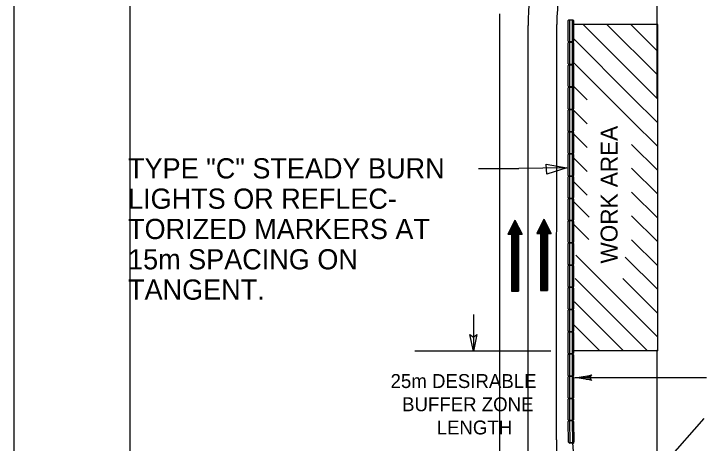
# Model space of a CAD drawing. Extents: x 2171 to 2395, y 134 to 413.
# Drawn here: x 2178.7 to 2238.8, y 319.6 to 356.6 of the extents above; entities that cross this region are included whole.
import ezdxf

# ---------------------------------------------------------------- set-up
doc = ezdxf.new("R2010")
doc.units = 0
for name, color, linetype in [('Level 10', 7, 'Continuous'), ('Level 12', 7, 'Continuous'), ('Level 2', 7, 'Continuous'), ('Level 20', 7, 'Continuous'), ('Level 4', 7, 'Continuous'), ('Level 5', 7, 'Continuous'), ('Level 60', 7, 'Continuous')]:
    doc.layers.add(name, color=color, linetype=linetype)

msp = doc.modelspace()

# ---------------------------------------------------------------- linework, layer by layer
at = {"layer": 'Level 10'}
for p, q in [((2220.618, 353.23), (2220.618, 356.607)), ((2234.222, 355.706), (2226.963, 355.706)), ((2226.963, 327.562), (2226.963, 355.706)), ((2234.222, 349.278), (2227.794, 355.706)), ((2234.222, 351.33), (2229.847, 355.706)), ((2234.222, 353.383), (2231.899, 355.706)), ((2234.222, 327.588), (2234.222, 355.706)), ((2223.061, 316.436), (2223.061, 355.61)), ((2232.007, 349.439), (2226.963, 354.483)), ((2220.618, 321.299), (2220.618, 353.23)), ((2232.086, 347.308), (2226.963, 352.431)), ((2228.139, 349.202), (2226.963, 350.378)), ((2234.222, 347.225), (2231.977, 349.47)), ((2228.139, 347.15), (2226.963, 348.326)), ((2234.222, 345.172), (2231.977, 347.417)), ((2228.139, 345.097), (2226.963, 346.273)), ((2234.222, 343.12), (2231.977, 345.365)), ((2228.139, 343.044), (2226.963, 344.22)), ((2218.779, 343.303), (2222.263, 343.303)), ((2226.386, 343.338), (2222.263, 343.303)), ((2234.222, 341.067), (2231.977, 343.312)), ((2228.139, 340.991), (2226.963, 342.168)), ((2234.222, 339.015), (2231.977, 341.259)), ((2228.324, 339.091), (2226.923, 340.491)), ((2221.917, 338.85), (2221.303, 337.622)), ((2221.917, 338.85), (2221.917, 332.714)), ((2221.917, 338.85), (2222.53, 337.622)), ((2224.422, 338.917), (2223.808, 337.69)), ((2224.422, 338.917), (2224.422, 332.781)), ((2224.422, 338.917), (2225.035, 337.69)), ((2234.222, 336.962), (2231.977, 339.206)), ((2221.611, 338.236), (2221.611, 332.714)), ((2221.687, 338.389), (2221.687, 332.714)), ((2221.762, 338.542), (2221.762, 332.714)), ((2221.841, 338.696), (2221.841, 332.714)), ((2221.993, 338.696), (2221.993, 332.714)), ((2222.07, 338.542), (2222.07, 332.714)), ((2222.147, 338.389), (2222.147, 332.714)), ((2222.224, 338.236), (2222.224, 332.714)), ((2224.116, 338.303), (2224.116, 332.781)), ((2224.192, 338.456), (2224.192, 332.781)), ((2224.268, 338.61), (2224.268, 332.781)), ((2224.346, 338.763), (2224.346, 332.781)), ((2224.498, 338.763), (2224.498, 332.781)), ((2224.575, 338.61), (2224.575, 332.781)), ((2224.652, 338.456), (2224.652, 332.781)), ((2224.729, 338.303), (2224.729, 332.781)), ((2228.276, 337.174), (2226.875, 338.575)), ((2221.303, 337.622), (2221.611, 337.622)), ((2221.38, 337.776), (2221.38, 337.622)), ((2221.456, 337.929), (2221.456, 337.622)), ((2221.533, 338.083), (2221.533, 337.622)), ((2221.611, 337.622), (2221.611, 332.714)), ((2222.224, 337.622), (2222.224, 332.714)), ((2222.224, 337.622), (2222.53, 337.622)), ((2222.3, 338.083), (2222.3, 337.622)), ((2222.377, 337.929), (2222.377, 337.622)), ((2222.454, 337.776), (2222.454, 337.622)), ((2223.808, 337.69), (2224.116, 337.69)), ((2223.885, 337.843), (2223.885, 337.69)), ((2223.961, 337.997), (2223.961, 337.69)), ((2224.038, 338.15), (2224.038, 337.69)), ((2224.116, 337.69), (2224.116, 332.781)), ((2224.729, 337.69), (2224.729, 332.781)), ((2224.729, 337.69), (2225.035, 337.69)), ((2224.806, 338.15), (2224.806, 337.69)), ((2224.882, 337.997), (2224.882, 337.69)), ((2224.959, 337.843), (2224.959, 337.69)), ((2234.222, 334.909), (2231.977, 337.154)), ((2234.222, 328.751), (2227.156, 335.817)), ((2234.222, 332.857), (2231.421, 335.658)), ((2233.324, 327.596), (2227.112, 333.809)), ((2234.222, 330.804), (2231.215, 333.811)), ((2221.611, 332.714), (2222.224, 332.714)), ((2224.116, 332.781), (2224.729, 332.781)), ((2231.253, 327.615), (2227.062, 331.807)), ((2229.181, 327.634), (2227.016, 329.798)), ((2234.222, 327.588), (2226.963, 327.588)), ((2234.222, 327.681), (2234.13, 327.589)), ((2220.618, 316.779), (2220.618, 321.81))]:
    msp.add_line(p, q, dxfattribs=at)
for points in [[(2224.62, 343.663), (2226.386, 343.338), (2224.675, 342.794)], [(2218.345, 327.544), (2218.043, 328.997), (2218.343, 328.757), (2218.643, 328.997)]]:
    msp.add_lwpolyline(points, close=True, dxfattribs=at)
at = {"layer": 'Level 12'}
for centre, radius, start, end in [((2245.532, 355.695), 20, 150.60658, 179.96375), ((2253.061, 355.61), 30, 161.99953, 180), ((2275.509, 319.886), 50, 179.96375, 194.28707)]:
    msp.add_arc(centre, radius, start, end, dxfattribs=at)
at = {"layer": 'Level 2'}
for p, q in [((2218.345, 330.718), (2218.345, 327.544)), ((2225.006, 327.544), (2213.297, 327.544))]:
    msp.add_line(p, q, dxfattribs=at)
at = {"layer": 'Level 20'}
for p, q in [((2234.164, 349.415), (2234.164, 399.312)), ((2234.164, 177.843), (2234.164, 327.612))]:
    msp.add_line(p, q, dxfattribs=at)
at = {"layer": 'Level 4'}
for p, q in [((2225.509, 319.917), (2225.532, 355.707)), ((2226.499, 354.26), (2226.5, 356.048)), ((2226.5, 356.048), (2226.566, 356.113)), ((2226.566, 356.113), (2226.897, 356.112)), ((2226.616, 356.113), (2226.613, 354.195)), ((2226.845, 356.114), (2226.843, 354.194)), ((2226.963, 356.048), (2226.897, 356.112)), ((2226.963, 356.048), (2226.961, 354.259)), ((2226.564, 354.195), (2226.499, 354.26)), ((2226.499, 352.321), (2226.5, 354.108)), ((2226.5, 354.108), (2226.566, 354.173)), ((2226.895, 354.195), (2226.564, 354.195)), ((2226.566, 354.173), (2226.897, 354.173)), ((2226.616, 354.173), (2226.613, 352.256)), ((2226.845, 354.174), (2226.843, 352.255)), ((2226.961, 354.259), (2226.895, 354.195)), ((2226.963, 354.109), (2226.897, 354.173)), ((2226.963, 354.109), (2226.961, 352.32)), ((2226.564, 352.255), (2226.499, 352.321)), ((2226.499, 350.382), (2226.5, 352.169)), ((2226.5, 352.169), (2226.566, 352.234)), ((2226.895, 352.256), (2226.564, 352.255)), ((2226.566, 352.234), (2226.897, 352.234)), ((2226.616, 352.234), (2226.613, 350.317)), ((2226.845, 352.235), (2226.843, 350.316)), ((2226.961, 352.32), (2226.895, 352.256)), ((2226.963, 352.169), (2226.897, 352.234)), ((2226.963, 352.169), (2226.961, 350.381)), ((2226.564, 350.316), (2226.499, 350.382)), ((2226.499, 348.441), (2226.5, 350.228)), ((2226.5, 350.228), (2226.566, 350.293)), ((2226.895, 350.317), (2226.564, 350.316)), ((2226.566, 350.293), (2226.897, 350.293)), ((2226.616, 350.293), (2226.613, 348.376)), ((2226.845, 350.294), (2226.843, 348.375)), ((2226.961, 350.381), (2226.895, 350.317)), ((2226.963, 350.229), (2226.897, 350.293)), ((2226.963, 350.229), (2226.961, 348.44)), ((2226.564, 348.376), (2226.499, 348.441)), ((2226.961, 348.44), (2226.895, 348.376)), ((2226.499, 346.524), (2226.5, 348.312)), ((2226.5, 348.312), (2226.566, 348.377)), ((2226.895, 348.376), (2226.564, 348.376)), ((2226.566, 348.377), (2226.897, 348.377)), ((2226.616, 348.377), (2226.613, 346.46)), ((2226.845, 348.378), (2226.843, 346.458)), ((2226.963, 348.312), (2226.897, 348.377)), ((2226.963, 348.312), (2226.961, 346.524)), ((2226.564, 346.459), (2226.499, 346.524)), ((2226.499, 344.609), (2226.5, 346.397)), ((2226.5, 346.397), (2226.566, 346.462)), ((2226.895, 346.46), (2226.564, 346.459)), ((2226.566, 346.462), (2226.897, 346.462)), ((2226.616, 346.462), (2226.613, 344.545)), ((2226.845, 346.463), (2226.843, 344.543)), ((2226.961, 346.524), (2226.895, 346.46)), ((2226.963, 346.397), (2226.897, 346.462)), ((2226.963, 346.397), (2226.961, 344.609)), ((2226.564, 344.544), (2226.499, 344.609)), ((2226.499, 342.694), (2226.5, 344.482)), ((2226.5, 344.482), (2226.566, 344.547)), ((2226.895, 344.544), (2226.564, 344.544)), ((2226.566, 344.547), (2226.897, 344.546)), ((2226.616, 344.547), (2226.613, 342.629)), ((2226.845, 344.548), (2226.843, 342.628)), ((2226.961, 344.609), (2226.895, 344.544)), ((2226.963, 344.482), (2226.897, 344.546)), ((2226.963, 344.482), (2226.961, 342.693)), ((2226.564, 342.629), (2226.499, 342.694)), ((2226.499, 340.779), (2226.5, 342.567)), ((2226.5, 342.567), (2226.566, 342.632)), ((2226.895, 342.629), (2226.564, 342.629)), ((2226.566, 342.632), (2226.897, 342.631)), ((2226.616, 342.632), (2226.613, 340.714)), ((2226.845, 342.632), (2226.843, 340.713)), ((2226.961, 342.693), (2226.895, 342.629)), ((2226.963, 342.567), (2226.897, 342.631)), ((2226.963, 342.567), (2226.961, 340.778)), ((2226.564, 340.714), (2226.499, 340.779)), ((2226.499, 338.864), (2226.5, 340.652)), ((2226.5, 340.652), (2226.566, 340.717)), ((2226.895, 340.714), (2226.564, 340.714)), ((2226.566, 340.717), (2226.897, 340.716)), ((2226.616, 340.717), (2226.613, 338.799)), ((2226.845, 340.717), (2226.843, 338.798)), ((2226.961, 340.778), (2226.895, 340.714)), ((2226.963, 340.652), (2226.897, 340.716)), ((2226.963, 340.652), (2226.961, 338.863)), ((2226.564, 338.799), (2226.499, 338.864)), ((2226.961, 338.863), (2226.895, 338.799)), ((2226.499, 336.949), (2226.5, 338.737)), ((2226.5, 338.737), (2226.566, 338.802)), ((2226.895, 338.799), (2226.564, 338.799)), ((2226.566, 338.802), (2226.897, 338.801)), ((2226.616, 338.802), (2226.613, 336.884)), ((2226.845, 338.802), (2226.843, 336.883)), ((2226.963, 338.737), (2226.897, 338.801)), ((2226.963, 338.737), (2226.961, 336.948)), ((2226.564, 336.884), (2226.499, 336.949)), ((2226.499, 335.034), (2226.5, 336.821)), ((2226.5, 336.821), (2226.566, 336.886)), ((2226.895, 336.884), (2226.564, 336.884)), ((2226.566, 336.886), (2226.897, 336.886)), ((2226.616, 336.886), (2226.613, 334.969)), ((2226.845, 336.887), (2226.843, 334.968)), ((2226.961, 336.948), (2226.895, 336.884)), ((2226.963, 336.822), (2226.897, 336.886)), ((2226.963, 336.822), (2226.961, 335.033)), ((2226.564, 334.968), (2226.499, 335.034)), ((2226.499, 333.119), (2226.5, 334.906)), ((2226.5, 334.906), (2226.566, 334.971)), ((2226.895, 334.969), (2226.564, 334.968)), ((2226.566, 334.971), (2226.897, 334.971)), ((2226.616, 334.971), (2226.613, 333.054)), ((2226.845, 334.972), (2226.843, 333.053)), ((2226.961, 335.033), (2226.895, 334.969)), ((2226.963, 334.906), (2226.897, 334.971)), ((2226.963, 334.906), (2226.961, 333.118)), ((2226.564, 333.053), (2226.499, 333.119)), ((2226.499, 331.204), (2226.5, 332.991)), ((2226.5, 332.991), (2226.566, 333.056)), ((2226.895, 333.054), (2226.564, 333.053)), ((2226.566, 333.056), (2226.897, 333.056)), ((2226.616, 333.056), (2226.613, 331.139)), ((2226.845, 333.057), (2226.843, 331.138)), ((2226.961, 333.118), (2226.895, 333.054)), ((2226.963, 332.991), (2226.897, 333.056)), ((2226.963, 332.991), (2226.961, 331.203)), ((2226.564, 331.138), (2226.499, 331.204)), ((2226.499, 329.289), (2226.5, 331.076)), ((2226.5, 331.076), (2226.566, 331.141)), ((2226.895, 331.139), (2226.564, 331.138)), ((2226.566, 331.141), (2226.897, 331.141)), ((2226.616, 331.141), (2226.613, 329.224)), ((2226.845, 331.142), (2226.843, 329.223)), ((2226.961, 331.203), (2226.895, 331.139)), ((2226.963, 331.076), (2226.897, 331.141)), ((2226.963, 331.076), (2226.961, 329.288)), ((2226.564, 329.223), (2226.499, 329.289)), ((2226.5, 329.161), (2226.566, 329.226)), ((2226.895, 329.224), (2226.564, 329.223)), ((2226.566, 329.226), (2226.897, 329.226)), ((2226.616, 329.226), (2226.613, 327.309)), ((2226.845, 329.227), (2226.843, 327.307)), ((2226.961, 329.288), (2226.895, 329.224)), ((2226.963, 329.161), (2226.897, 329.226)), ((2226.499, 327.373), (2226.5, 329.161)), ((2226.963, 329.161), (2226.961, 327.373)), ((2226.564, 327.308), (2226.499, 327.373)), ((2226.499, 325.458), (2226.5, 327.246)), ((2226.5, 327.246), (2226.566, 327.311)), ((2226.895, 327.309), (2226.564, 327.308)), ((2226.566, 327.311), (2226.897, 327.311)), ((2226.616, 327.311), (2226.613, 325.394)), ((2226.845, 327.312), (2226.843, 325.392)), ((2226.961, 327.373), (2226.895, 327.309)), ((2226.963, 327.246), (2226.897, 327.311)), ((2226.963, 327.246), (2226.961, 325.458)), ((2226.564, 325.393), (2226.499, 325.458)), ((2226.499, 323.543), (2226.5, 325.331)), ((2226.5, 325.331), (2226.566, 325.396)), ((2226.895, 325.393), (2226.564, 325.393)), ((2226.566, 325.396), (2226.897, 325.395)), ((2226.616, 325.396), (2226.613, 323.478)), ((2226.845, 325.397), (2226.843, 323.477)), ((2226.961, 325.458), (2226.895, 325.393)), ((2226.963, 325.331), (2226.897, 325.395)), ((2226.963, 325.331), (2226.961, 323.542)), ((2226.564, 323.478), (2226.499, 323.543)), ((2226.499, 321.628), (2226.5, 323.416)), ((2226.5, 323.416), (2226.566, 323.481)), ((2226.895, 323.478), (2226.564, 323.478)), ((2226.566, 323.481), (2226.897, 323.48)), ((2226.616, 323.481), (2226.613, 321.563)), ((2226.845, 323.482), (2226.843, 321.562)), ((2226.961, 323.542), (2226.895, 323.478)), ((2226.963, 323.416), (2226.897, 323.48)), ((2226.963, 323.416), (2226.961, 321.627)), ((2226.564, 321.563), (2226.499, 321.628)), ((2226.501, 321.492), (2226.566, 321.558)), ((2226.532, 319.705), (2226.501, 321.492)), ((2226.895, 321.563), (2226.564, 321.563)), ((2226.566, 321.558), (2226.897, 321.564)), ((2226.616, 321.559), (2226.648, 319.642)), ((2226.845, 321.564), (2226.878, 319.645)), ((2226.961, 321.627), (2226.895, 321.563)), ((2226.964, 321.5), (2226.897, 321.564)), ((2226.964, 321.5), (2226.994, 319.712)), ((2226.599, 319.64), (2226.532, 319.705)), ((2226.599, 319.622), (2226.929, 319.649)), ((2226.93, 319.647), (2226.599, 319.64)), ((2226.878, 319.645), (2227.034, 317.733)), ((2227, 319.59), (2226.929, 319.649)), ((2226.994, 319.712), (2226.93, 319.647))]:
    msp.add_line(p, q, dxfattribs=at)
at = {"layer": 'Level 5'}
for p, q in [((2238.436, 325.266), (2227.083, 325.266)), ((2228.056, 325.147), (2228.384, 325.148)), ((2228.074, 325.388), (2228.403, 325.39)), ((2238.207, 321.737), (2229.185, 311.591))]:
    msp.add_line(p, q, dxfattribs=at)
for centre, radius, start, end in [((2226.429, 333.535), 8.296, 274.51899, 284.68596), ((2226.392, 316.583), 8.709, 75.76919, 85.4469), ((2228.714, 325.267), 0.303, 126.74551, 233.23353)]:
    msp.add_arc(centre, radius, start, end, dxfattribs=at)
at = {"layer": 'Level 60'}
for points in [[(2394.748, 412.757), (2178.748, 412.757), (2178.748, 133.757), (2394.748, 133.757)], [(2375.622, 401.948), (2188.748, 401.948), (2188.748, 144.566), (2375.622, 144.566)]]:
    msp.add_lwpolyline(points, close=True, dxfattribs=at)

# ---------------------------------------------------------------- texts
at = {"layer": 'Level 10'}
msp.add_text('WORK AREA', height=1.4514, rotation=90, dxfattribs=at).set_placement((2230.759, 335.102))
for s, p in [('TYPE "C" STEADY BURN ', (2188.582, 342.432)), ('LIGHTS OR REFLEC-', (2188.582, 339.82)), ('TORIZED MARKERS AT ', (2188.582, 337.208)), ('15m SPACING ON ', (2188.582, 334.596)), ('TANGENT.', (2188.582, 331.984))]:
    msp.add_text(s, height=1.742, dxfattribs=at).set_placement(p)
at = {"layer": 'Level 60'}
for s, p in [('25m DESIRABLE', (2211.205, 324.376)), ('BUFFER ZONE', (2212.197, 322.376)), ('LENGTH', (2215.174, 320.376))]:
    msp.add_text(s, height=1.2, rotation=359.99999, dxfattribs=at).set_placement(p)

doc.saveas('drawing.dxf')
